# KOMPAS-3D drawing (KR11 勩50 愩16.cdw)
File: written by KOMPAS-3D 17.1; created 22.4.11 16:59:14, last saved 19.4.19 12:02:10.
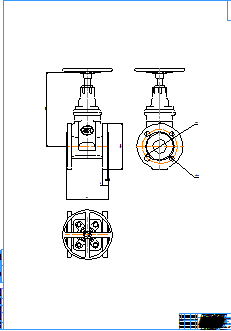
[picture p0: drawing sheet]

Title block, sheet 1: name: KR11 Ду50 Ру16; material: Внимание! Данный продукт является объектом авторского права ООО «Торговый Дом АДЛ». / Запрещается изменение, копирование, распространение / (в том числе путем копирования на другие сайты и ресурсы в Интернете) / или любое иное использование информации и объектов без предварительного / согласия правообладателя (ООО «Торговый Дом АДЛ»).; mass: 11; sheets: 1; organisation: ООО "Торговый дом АДЛ"; sheet format: A0; stored path: \\adlc.lan\data\АДЛ_ПКД\3D-модели\ADL production\Клиновые задвижки серии KR ГРАНАР\Клиновые задвижки KR11\KOMPAS 2D\KR11 Ду50 Ру16.cdw

Views: Спереди 4, Проекционный вид 5
Dimensions and other numbers on the sheet: 150; 19; 3; 165; 266; 1:1; 1; 11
